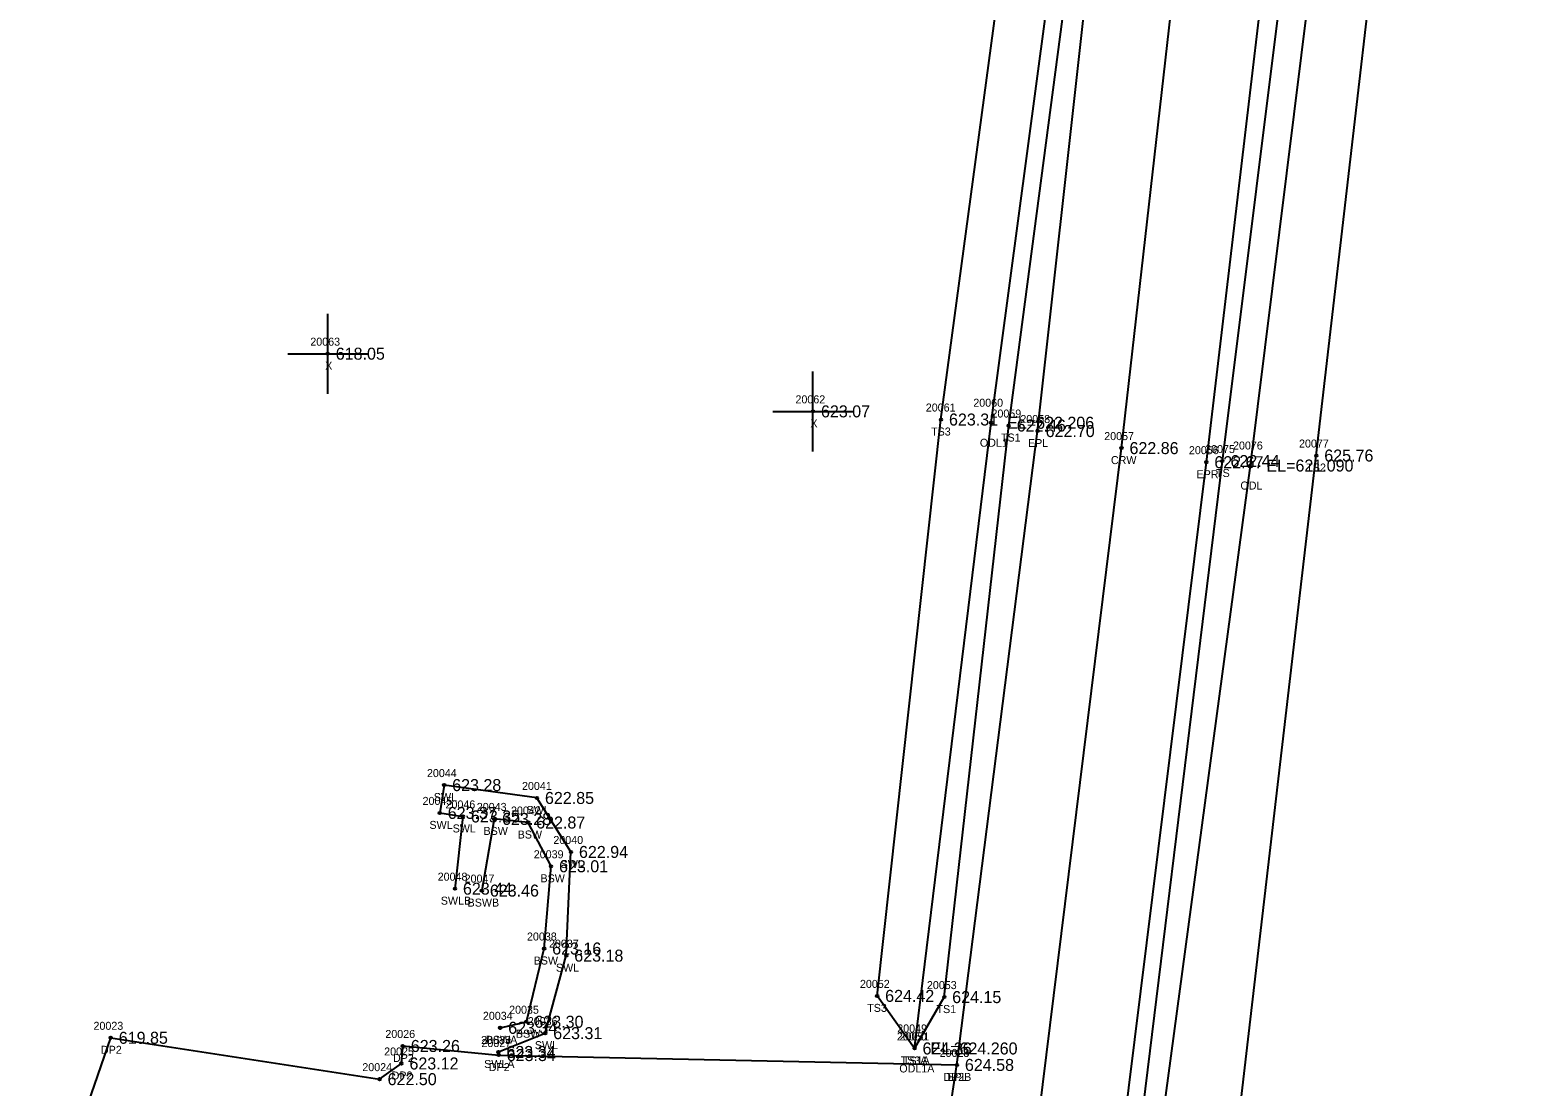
# Model space of a CAD drawing. Extents: x 1695443 to 1696344, y 1087542 to 1090645.
# Drawn here: x 1695771.6 to 1695957.9, y 1087791.5 to 1087923.6 of the extents above; entities that cross this region are included whole.
import ezdxf

# ---------------------------------------------------------------- set-up
doc = ezdxf.new("R2010")
doc.units = 0
for name, color, linetype in [('RD_DTM_BkLn1', 7, 'Continuous'), ('RD_DTM_BkLn2', 7, 'Continuous'), ('RD_DTM_BkLn_txCode', 7, 'Continuous'), ('RD_EX_Conc', 7, 'Continuous'), ('RD_EX_Conc_txCode', 7, 'Continuous'), ('RD_EX_Driveway', 7, 'Continuous'), ('RD_EX_Driveway_txCode', 7, 'Continuous'), ('RD_EX_H2O', 7, 'Continuous'), ('RD_EX_H2O_txCode', 7, 'Continuous'), ('RD_EX_Misc', 7, 'Continuous'), ('RD_EX_Misc_txCode', 7, 'Continuous'), ('RD_EX_Road', 7, 'Continuous'), ('RD_EX_Road_txCode', 7, 'Continuous'), ('RD_EX_TX_Conc_ELEV', 7, 'Continuous'), ('RD_EX_TX_Driveway_ELEV', 7, 'Continuous'), ('RD_EX_TX_H2O_ELEV', 7, 'Continuous'), ('RD_EX_TX_Misc_ELEV', 7, 'Continuous'), ('RD_EX_TX_Road_ELEV', 7, 'Continuous'), ('RD_HC_Survey_ELEV', 7, 'Continuous'), ('RD_HC_Survey_txCode', 7, 'Continuous'), ('RD_SMD_Locator', 7, 'Continuous')]:
    doc.layers.add(name, color=color, linetype=linetype)

msp = doc.modelspace()

# ---------------------------------------------------------------- linework, layer by layer
at = {"layer": 'RD_DTM_BkLn1'}
msp.add_lwpolyline([(1695869.23, 1087563.38), (1695882.71, 1087666.87), (1695895.39, 1087768.85), (1695908.05, 1087871.3), (1695919.71, 1087974.19), (1695925.35, 1088026.13), (1695931.27, 1088077.73), (1695937.88, 1088128.75), (1695945.4, 1088182.97), (1695952.48, 1088232.38), (1695961.74, 1088286.36), (1695971.36, 1088336.92), (1695982.91, 1088390.82), (1696009.16, 1088497.22), (1696035.45, 1088601.7), (1696045.5, 1088655.66), (1696049.03, 1088705.78), (1696045.47, 1088756.42), (1696033.82, 1088809.1), (1696016.78, 1088855.71), (1695990.89, 1088906.17), (1695964.41, 1088947.39), (1695931.21, 1088992.88)], dxfattribs=at)
at = {"layer": 'RD_DTM_BkLn2'}
for points in [[(1695882.6, 1087560.4), (1695895.55, 1087664.54), (1695908.06, 1087766.74), (1695920.67, 1087869.68), (1695933.47, 1087972.17), (1695938.06, 1088020.68), (1695943.39, 1088076.15), (1695950.93, 1088126.12), (1695958.62, 1088180.79), (1695967.59, 1088232.03), (1695975.32, 1088283.22), (1695985.14, 1088336.17), (1695996.59, 1088387.88), (1696023.18, 1088492.82), (1696049.23, 1088599.85), (1696058.32, 1088654.25)], [(1695882.6, 1087560.4), (1695883.79, 1087555.85), (1695890.5, 1087560.67), (1695906.06, 1087668.38), (1695920.19, 1087765.58), (1695932.4, 1087870.37), (1695944.02, 1087970.73), (1695947.56, 1088017.12), (1695952.59, 1088072.2), (1695957.06, 1088113.91)], [(1695882.18, 1087796.26), (1695885.89, 1087802.68), (1695893.96, 1087874.12), (1695907.45, 1087976.35), (1695913.13, 1088029.53), (1695914, 1088053.25)], [(1695882.18, 1087796.26), (1695877.51, 1087802.83), (1695885.49, 1087874.87), (1695898.91, 1087974.85), (1695905.04, 1088043.13), (1695857.41, 1088040.54), (1695824.61, 1088033.48)]]:
    msp.add_lwpolyline(points, dxfattribs=at)
at = {"layer": 'RD_EX_Conc'}
for points in [[(1695830.17, 1087795.82), (1695836.02, 1087798.17), (1695838.65, 1087807.86), (1695839.24, 1087820.82), (1695834.99, 1087827.57), (1695823.39, 1087829.18), (1695822.84, 1087825.7), (1695825.74, 1087825.26), (1695824.74, 1087816.23)], [(1695830.39, 1087798.84), (1695833.67, 1087799.6), (1695835.89, 1087808.75), (1695836.75, 1087819.03), (1695833.89, 1087824.5), (1695829.63, 1087824.95), (1695828.1, 1087815.99)]]:
    msp.add_lwpolyline(points, dxfattribs=at)
at = {"layer": 'RD_EX_Driveway'}
msp.add_lwpolyline([(1695771.6, 1087768.24), (1695781.72, 1087797.59), (1695815.32, 1087792.42), (1695818.05, 1087794.38), (1695818.22, 1087796.57), (1695830.21, 1087795.43), (1695887.48, 1087794.2)], dxfattribs=at)
at = {"layer": 'RD_EX_H2O'}
for points in [[(1695884.7, 1087558.83), (1695897.39, 1087664.39), (1695910.4, 1087766.5), (1695924.17, 1087869.12), (1695936.94, 1087971.73), (1695941.17, 1088019.96), (1695947.61, 1088073.49), (1695957.06, 1088113.91)], [(1695882.18, 1087796.26), (1695891.76, 1087874.47), (1695905.41, 1087976.74), (1695911.27, 1088029.23), (1695914, 1088053.25)]]:
    msp.add_lwpolyline(points, dxfattribs=at)
at = {"layer": 'RD_EX_Misc'}
for p, q in [((1695808.84, 1087878.1), (1695808.84, 1087888.1)), ((1695803.84, 1087883.1), (1695813.84, 1087883.1)), ((1695869.49, 1087870.89), (1695869.49, 1087880.89)), ((1695864.49, 1087875.89), (1695874.49, 1087875.89))]:
    msp.add_line(p, q, dxfattribs=at)
at = {"layer": 'RD_EX_Road'}
for points in [[(1695879.87, 1087561.29), (1695893.33, 1087665.71), (1695905.96, 1087767.16), (1695918.66, 1087869.54), (1695930.87, 1087972.82), (1695936.26, 1088023.68), (1695942.14, 1088076.32), (1695948.07, 1088128.17), (1695955.04, 1088181.4), (1695962.88, 1088230.72), (1695971.68, 1088284.64), (1695982.02, 1088336.12), (1695993.28, 1088388.48), (1696018.75, 1088494.48), (1696045.23, 1088599.95), (1696055.72, 1088654.41), (1696060.15, 1088705.35), (1696055.83, 1088758.02), (1696044.01, 1088812.16), (1696026.4, 1088860.33), (1696000.41, 1088911.48), (1695972.46, 1088953.82), (1695939.48, 1088998.73), (1695931.21, 1088992.88)], [(1695858.19, 1087564.9), (1695871.71, 1087668.82), (1695884.5, 1087774.69), (1695887.48, 1087794.2), (1695897.57, 1087873.43), (1695908.92, 1087975.76), (1695914.49, 1088029.24), (1695917.65, 1088054.8), (1695920.27, 1088079.09), (1695926.98, 1088130.26), (1695934.75, 1088185.09), (1695942.15, 1088234.62), (1695951.36, 1088288.06), (1695961.48, 1088338.41), (1695972.86, 1088394.13), (1695998.53, 1088499.67), (1696024.81, 1088603.86), (1696034.83, 1088656.78)]]:
    msp.add_lwpolyline(points, dxfattribs=at)
at = {"layer": 'RD_SMD_Locator'}
for centre in [(1695808.84, 1087883.1), (1695869.49, 1087875.89), (1695885.49, 1087874.87), (1695891.76, 1087874.47), (1695893.96, 1087874.12), (1695897.57, 1087873.43), (1695908.05, 1087871.3), (1695918.66, 1087869.54), (1695920.67, 1087869.68), (1695924.17, 1087869.12), (1695932.4, 1087870.37), (1695823.39, 1087829.18), (1695834.99, 1087827.57), (1695822.84, 1087825.7), (1695825.74, 1087825.26), (1695829.63, 1087824.95), (1695833.89, 1087824.5), (1695839.24, 1087820.82), (1695836.75, 1087819.03), (1695824.74, 1087816.23), (1695828.1, 1087815.99), (1695835.89, 1087808.75), (1695838.65, 1087807.86), (1695877.51, 1087802.83), (1695885.89, 1087802.68), (1695830.39, 1087798.84), (1695833.67, 1087799.6), (1695836.02, 1087798.17), (1695781.72, 1087797.59), (1695818.22, 1087796.57), (1695830.17, 1087795.82), (1695830.21, 1087795.43), (1695882.18, 1087796.26), (1695882.18, 1087796.26), (1695882.18, 1087796.26), (1695818.05, 1087794.38), (1695887.48, 1087794.2), (1695887.48, 1087794.2), (1695815.32, 1087792.42)]:
    msp.add_circle(centre, 0.15, dxfattribs=at)

# ---------------------------------------------------------------- texts
at = {"layer": 'RD_DTM_BkLn_txCode'}
for s, p in [('20061', (1695883.59, 1087875.87)), ('20059', (1695891.8, 1087875.12)), ('TS3', (1695884.25, 1087872.87)), ('TS1', (1695892.99, 1087872.12)), ('20075', (1695918.51, 1087870.68)), ('20077', (1695930.24, 1087871.37)), ('TS2', (1695931.15, 1087868.37)), ('TS', (1695919.87, 1087867.68)), ('20052', (1695875.36, 1087803.83)), ('20053', (1695883.73, 1087803.68)), ('TS3', (1695876.27, 1087800.83)), ('TS1', (1695884.93, 1087800.68)), ('20050', (1695879.98, 1087797.26)), ('20051', (1695880.31, 1087797.26)), ('TS3A', (1695880.45, 1087794.26)), ('TS1A', (1695880.73, 1087794.26))]:
    msp.add_text(s, height=1, dxfattribs=at).set_placement(p)
at = {"layer": 'RD_EX_Conc_txCode'}
for s, p in [('20044', (1695821.24, 1087830.18)), ('SWL', (1695822.1, 1087827.18)), ('20041', (1695833.12, 1087828.57)), ('20045', (1695820.69, 1087826.7)), ('20046', (1695823.56, 1087826.26)), ('20043', (1695827.47, 1087825.95)), ('20042', (1695831.74, 1087825.5)), ('SWL', (1695833.7, 1087825.57)), ('SWL', (1695821.55, 1087823.7)), ('SWL', (1695824.45, 1087823.26)), ('BSW', (1695828.31, 1087822.95)), ('BSW', (1695832.58, 1087822.5)), ('20040', (1695837.04, 1087821.82)), ('20039', (1695834.59, 1087820.03)), ('SWL', (1695837.95, 1087818.82)), ('20048', (1695822.58, 1087817.23)), ('20047', (1695825.95, 1087816.99)), ('BSW', (1695835.43, 1087817.03)), ('SWLB', (1695822.97, 1087814.23)), ('BSWB', (1695826.32, 1087813.99)), ('20038', (1695833.74, 1087809.75)), ('20037', (1695836.49, 1087808.86)), ('BSW', (1695834.58, 1087806.75)), ('SWL', (1695837.36, 1087805.86)), ('20034', (1695828.23, 1087799.84)), ('20035', (1695831.51, 1087800.6)), ('20036', (1695833.84, 1087799.17)), ('BSW', (1695832.36, 1087797.6)), ('20033', (1695828.01, 1087796.82)), ('BSWA', (1695828.59, 1087796.84)), ('SWL', (1695834.73, 1087796.17)), ('SWLA', (1695828.39, 1087793.82))]:
    msp.add_text(s, height=1, dxfattribs=at).set_placement(p)
at = {"layer": 'RD_EX_Driveway_txCode'}
for s, p in [('20023', (1695779.56, 1087798.59)), ('20026', (1695816.04, 1087797.57)), ('DP2', (1695780.49, 1087795.59)), ('20027', (1695828.05, 1087796.43)), ('20025', (1695815.89, 1087795.38)), ('DP2', (1695816.99, 1087794.57)), ('20028', (1695885.32, 1087795.2)), ('20024', (1695813.16, 1087793.42)), ('DP2', (1695816.82, 1087792.38)), ('DP2', (1695828.98, 1087793.43)), ('DP2B', (1695885.78, 1087792.2))]:
    msp.add_text(s, height=1, dxfattribs=at).set_placement(p)
at = {"layer": 'RD_EX_H2O_txCode'}
for s, p in [('20060', (1695889.53, 1087876.47)), ('ODL1', (1695890.35, 1087871.47)), ('20076', (1695921.99, 1087871.12)), ('ODL', (1695922.92, 1087866.12)), ('20049', (1695880.02, 1087798.26)), ('ODL1A', (1695880.28, 1087793.26))]:
    msp.add_text(s, height=1, dxfattribs=at).set_placement(p)
at = {"layer": 'RD_EX_Misc_txCode'}
for s, p in [('20063', (1695806.66, 1087884.1)), ('X', (1695808.52, 1087881.1)), ('20062', (1695867.3, 1087876.89)), ('X', (1695869.17, 1087873.89))]:
    msp.add_text(s, height=1, dxfattribs=at).set_placement(p)
at = {"layer": 'RD_EX_Road_txCode'}
for s, p in [('20058', (1695895.41, 1087874.43)), ('EPL', (1695896.36, 1087871.43)), ('20056', (1695916.48, 1087870.54)), ('EPR', (1695917.43, 1087867.54)), ('20029', (1695885.32, 1087795.2)), ('EPL', (1695886.28, 1087792.2))]:
    msp.add_text(s, height=1, dxfattribs=at).set_placement(p)
at = {"layer": 'RD_EX_TX_Conc_ELEV'}
for s, p in [('623.28', (1695824.39, 1087828.43)), ('622.85', (1695835.99, 1087826.82)), ('623.37', (1695823.84, 1087824.95)), ('623.35', (1695826.74, 1087824.51)), ('623.28', (1695830.63, 1087824.2)), ('622.87', (1695834.89, 1087823.75)), ('622.94', (1695840.24, 1087820.07)), ('623.01', (1695837.75, 1087818.28)), ('623.44', (1695825.74, 1087815.48)), ('623.46', (1695829.1, 1087815.24)), ('623.16', (1695836.89, 1087808)), ('623.18', (1695839.65, 1087807.11)), ('623.30', (1695834.67, 1087798.85)), ('623.34', (1695831.39, 1087798.09)), ('623.31', (1695837.02, 1087797.42)), ('623.34', (1695831.17, 1087795.07))]:
    msp.add_text(s, height=1.5, dxfattribs=at).set_placement(p)
at = {"layer": 'RD_EX_TX_Driveway_ELEV'}
for s, p in [('619.85', (1695782.72, 1087796.84)), ('623.26', (1695819.22, 1087795.82)), ('623.12', (1695819.05, 1087793.63)), ('623.34', (1695831.21, 1087794.68)), ('624.58', (1695888.48, 1087793.45)), ('622.50', (1695816.32, 1087791.67))]:
    msp.add_text(s, height=1.5, dxfattribs=at).set_placement(p)
at = {"layer": 'RD_EX_TX_H2O_ELEV'}
for s, p in [('EL=622.206', (1695893.76, 1087873.72)), ('EL=621.090', (1695926.17, 1087868.37)), ('EL=624.260', (1695884.18, 1087795.51))]:
    msp.add_text(s, height=1.5, dxfattribs=at).set_placement(p)
at = {"layer": 'RD_EX_TX_Misc_ELEV'}
for s, p in [('618.05', (1695809.84, 1087882.35)), ('623.07', (1695870.49, 1087875.14)), ('623.31', (1695886.49, 1087874.12)), ('622.46', (1695894.96, 1087873.37)), ('625.76', (1695933.4, 1087869.62)), ('622.44', (1695921.67, 1087868.93)), ('624.42', (1695878.51, 1087802.08)), ('624.15', (1695886.89, 1087801.93)), ('624.26', (1695883.18, 1087795.51)), ('624.26', (1695883.18, 1087795.51))]:
    msp.add_text(s, height=1.5, dxfattribs=at).set_placement(p)
at = {"layer": 'RD_EX_TX_Road_ELEV'}
for s, p in [('622.70', (1695898.57, 1087872.68)), ('622.67', (1695919.66, 1087868.79)), ('624.58', (1695888.48, 1087793.45))]:
    msp.add_text(s, height=1.5, dxfattribs=at).set_placement(p)
at = {"layer": 'RD_HC_Survey_ELEV'}
msp.add_text('622.86', height=1.5, dxfattribs=at).set_placement((1695909.05, 1087870.55))
at = {"layer": 'RD_HC_Survey_txCode'}
for s, p in [('20057', (1695905.89, 1087872.3)), ('CRW', (1695906.73, 1087869.3))]:
    msp.add_text(s, height=1, dxfattribs=at).set_placement(p)

doc.saveas('drawing.dxf')
